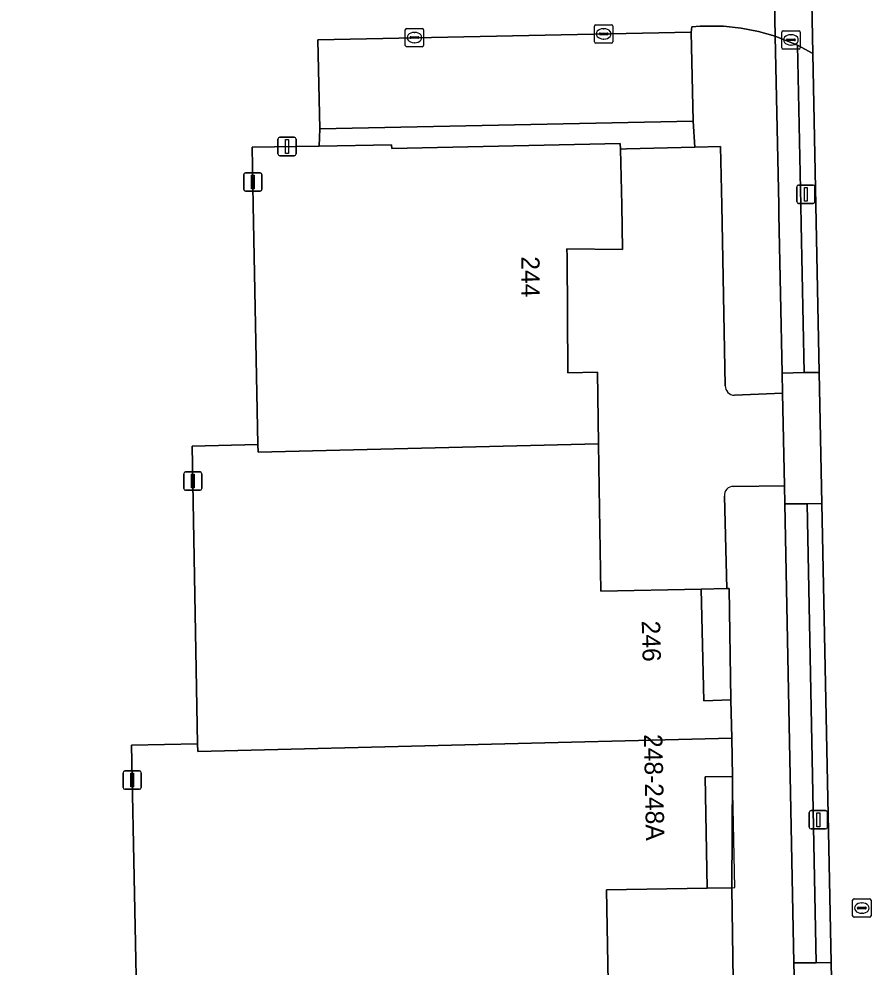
# Model space of a CAD drawing. Extents: x 161385 to 162589, y 388479 to 389756.
# Drawn here: x 162447.9 to 162494.3, y 388958.5 to 389010.1 of the extents above; entities that cross this region are included whole.
import ezdxf

# ---------------------------------------------------------------- set-up
doc = ezdxf.new("R2010")
doc.units = 0
for name, color, linetype in [('IMGEO_Berm_groen', 7, 'Continuous'), ('IMGEO_Brandkraan', 7, 'Continuous'), ('IMGEO_Erf', 7, 'Continuous'), ('IMGEO_Groenvoorziening', 7, 'Continuous'), ('IMGEO_Kolk', 7, 'Continuous'), ('IMGEO_Lichtmast', 7, 'Continuous'), ('IMGEO_Pand', 7, 'Continuous'), ('IMGEO_Pand_nummerreeks', 7, 'Continuous'), ('IMGEO_Pand_overbouw', 7, 'Continuous'), ('IMGEO_Parkeervlak_open', 7, 'Continuous'), ('IMGEO_Rijbaan_lokaal_gesloten', 7, 'Continuous'), ('IMGEO_Rijbaan_lokaal_open', 7, 'Continuous'), ('IMGEO_Rioolput', 7, 'Continuous'), ('IMGEO_Voetpad_open', 7, 'Continuous')]:
    doc.layers.add(name, color=color, linetype=linetype)

msp = doc.modelspace()

# ---------------------------------------------------------------- linework, layer by layer
at = {"layer": 'IMGEO_Berm_groen'}
for points in [[(162491.322, 389000), (162491.156, 389008.259), (162490.312, 389008.711), (162490.501, 389000), (162490.524, 388998.957), (162490.684, 388990.89), (162491.505, 388990.892)], [(162491.649, 388983.772), (162490.848, 388983.753), (162491.33, 388958.751), (162492.152, 388958.778)]]:
    msp.add_lwpolyline(points, close=True, dxfattribs=at)
at = {"layer": 'IMGEO_Brandkraan'}
for p, q in [((162489.536, 389009.503), (162490.388, 389009.503)), ((162489.461, 389008.577), (162489.461, 389009.429)), ((162489.72, 389008.997), (162489.72, 389009.009)), ((162489.763, 389009.046), (162490.161, 389009.046)), ((162489.949, 389009.283), (162489.974, 389009.283)), ((162490.204, 389009.009), (162490.204, 389008.997)), ((162490.462, 389009.429), (162490.462, 389008.577)), ((162490.388, 389008.503), (162489.536, 389008.503)), ((162490.158, 389008.96), (162489.76, 389008.96)), ((162489.972, 389008.723), (162489.947, 389008.723))]:
    msp.add_line(p, q, dxfattribs=at)
for points in [[(162489.536, 389009.503), (162490.388, 389009.503)], [(162489.461, 389008.577), (162489.461, 389009.429)], [(162490.462, 389009.429), (162490.462, 389008.577)], [(162490.388, 389008.503), (162489.536, 389008.503)]]:
    msp.add_lwpolyline(points, dxfattribs=at)
for centre, radius, start, end in [((162489.538, 389009.427), 0.0765, 91.552, 178.448), ((162489.538, 389009.427), 0.0765, 91.552, 178.448), ((162490.386, 389009.427), 0.0765, 1.552, 88.448), ((162490.386, 389009.427), 0.0765, 1.552, 88.448), ((162489.76, 389009.006), 0.0403, 85.8775, 175.7526), ((162489.757, 389008.996), 0.0366, 178.938, 274.7102), ((162490.161, 389009.003), 0.043, 264.8664, 352.4533), ((162490.165, 389009.008), 0.0386, 1.7309, 96.639), ((162489.538, 389008.579), 0.0765, 181.552, 268.448), ((162489.538, 389008.579), 0.0765, 181.552, 268.448), ((162490.386, 389008.579), 0.0765, 271.552, 358.448), ((162490.386, 389008.579), 0.0765, 271.552, 358.448)]:
    msp.add_arc(centre, radius, start, end, dxfattribs=at)
for centre, major_axis, ratio, start_param, end_param in [((162489.948, 389009.003), (-0.387, 0.002), 0.722429, 4.712389, 7.853982), ((162489.973, 389009.003), (-0.39, 0.002), 0.717154, 1.570796, 4.712389)]:
    msp.add_ellipse(centre, major_axis=major_axis, ratio=ratio, start_param=start_param, end_param=end_param, dxfattribs=at)
at = {"layer": 'IMGEO_Erf'}
for points in [[(162485.082, 388979.109), (162485.22, 388973.029), (162486.699, 388973.085), (162486.603, 388979.144), (162486.474, 388979.141)], [(162486.738, 388962.839), (162486.781, 388968.908), (162485.287, 388968.877), (162485.411, 388962.828)]]:
    msp.add_lwpolyline(points, close=True, dxfattribs=at)
at = {"layer": 'IMGEO_Groenvoorziening'}
for points in [[(162486.89, 388989.661), (162489.504, 388989.767), (162489.482, 388990.868), (162489.306, 388999.491), (162489.295, 389000), (162489.105, 389009.202), (162488.187, 389009.466), (162487.248, 389009.648), (162486.298, 389009.744), (162485.342, 389009.756), (162485.013, 389009.74), (162484.565, 389009.708), (162484.537, 389009.425), (162484.639, 389004.582), (162484.722, 389003.167), (162486.131, 389003.204), (162486.193, 389000), (162486.383, 388990.175)], [(162486.34, 388984.168), (162486.474, 388979.141), (162486.603, 388979.144), (162486.699, 388973.085), (162486.74, 388970.982), (162486.781, 388968.908), (162486.738, 388962.839), (162486.818, 388957.815), (162486.995, 388957.473), (162487.344, 388957.311), (162490.163, 388957.43), (162490.121, 388958.751), (162489.634, 388983.74), (162489.607, 388984.73), (162486.835, 388984.698)]]:
    msp.add_lwpolyline(points, dxfattribs=at)
for centre, radius, start, end in [((162486.887, 388990.165), 0.504, 178.8345, 270.3799), ((162486.83, 388984.206), 0.492, 89.458, 184.4534)]:
    msp.add_arc(centre, radius, start, end, dxfattribs=at)
at = {"layer": 'IMGEO_Kolk'}
for p, q in [((162468.969, 389008.704), (162468.969, 389009.556)), ((162469.044, 389009.63), (162469.896, 389009.63)), ((162469.97, 389009.556), (162469.97, 389008.704)), ((162479.271, 389008.903), (162479.271, 389009.755)), ((162479.346, 389009.829), (162480.198, 389009.829)), ((162479.759, 389009.609), (162479.784, 389009.609)), ((162480.272, 389009.755), (162480.272, 389008.903)), ((162469.228, 389009.124), (162469.228, 389009.136)), ((162469.666, 389009.087), (162469.268, 389009.087)), ((162469.271, 389009.173), (162469.669, 389009.173)), ((162469.457, 389009.41), (162469.482, 389009.41)), ((162469.712, 389009.136), (162469.712, 389009.124)), ((162479.53, 389009.323), (162479.53, 389009.335)), ((162479.968, 389009.286), (162479.57, 389009.286)), ((162479.573, 389009.372), (162479.971, 389009.372)), ((162479.782, 389009.049), (162479.757, 389009.049)), ((162480.014, 389009.335), (162480.014, 389009.323)), ((162469.896, 389008.63), (162469.044, 389008.63)), ((162469.48, 389008.85), (162469.455, 389008.85)), ((162480.198, 389008.829), (162479.346, 389008.829))]:
    msp.add_line(p, q, dxfattribs=at)
for points in [[(162468.969, 389008.704), (162468.969, 389009.556)], [(162469.044, 389009.63), (162469.896, 389009.63)], [(162469.97, 389009.556), (162469.97, 389008.704)], [(162479.271, 389008.903), (162479.271, 389009.755)], [(162479.346, 389009.829), (162480.198, 389009.829)], [(162480.272, 389009.755), (162480.272, 389008.903)], [(162469.896, 389008.63), (162469.044, 389008.63)], [(162480.198, 389008.829), (162479.346, 389008.829)]]:
    msp.add_lwpolyline(points, dxfattribs=at)
for centre, radius, start, end in [((162469.046, 389009.554), 0.0765, 91.552, 178.448), ((162469.046, 389009.554), 0.0765, 91.552, 178.448), ((162469.894, 389009.554), 0.0765, 1.552, 88.448), ((162469.894, 389009.554), 0.0765, 1.552, 88.448), ((162479.348, 389009.753), 0.0765, 91.552, 178.448), ((162479.348, 389009.753), 0.0765, 91.552, 178.448), ((162480.196, 389009.753), 0.0765, 1.552, 88.448), ((162480.196, 389009.753), 0.0765, 1.552, 88.448), ((162469.268, 389009.133), 0.0403, 85.8775, 175.7526), ((162469.265, 389009.123), 0.0366, 178.938, 274.7102), ((162469.669, 389009.13), 0.043, 264.8664, 352.4533), ((162469.673, 389009.135), 0.0386, 1.7309, 96.639), ((162479.57, 389009.332), 0.0403, 85.8775, 175.7526), ((162479.567, 389009.322), 0.0366, 178.938, 274.7102), ((162479.971, 389009.329), 0.043, 264.8664, 352.4533), ((162479.975, 389009.334), 0.0386, 1.7309, 96.639), ((162469.046, 389008.706), 0.0765, 181.552, 268.448), ((162469.046, 389008.706), 0.0765, 181.552, 268.448), ((162469.894, 389008.706), 0.0765, 271.552, 358.448), ((162469.894, 389008.706), 0.0765, 271.552, 358.448), ((162479.348, 389008.905), 0.0765, 181.552, 268.448), ((162479.348, 389008.905), 0.0765, 181.552, 268.448), ((162480.196, 389008.905), 0.0765, 271.552, 358.448), ((162480.196, 389008.905), 0.0765, 271.552, 358.448)]:
    msp.add_arc(centre, radius, start, end, dxfattribs=at)
for centre, major_axis, ratio, start_param, end_param in [((162479.758, 389009.329), (-0.387, 0.002), 0.722429, 4.712389, 7.853982), ((162479.783, 389009.329), (-0.39, 0.002), 0.717154, 1.570796, 4.712389), ((162469.456, 389009.13), (-0.387, 0.002), 0.722429, 4.712389, 7.853982), ((162469.481, 389009.13), (-0.39, 0.002), 0.717154, 1.570796, 4.712389)]:
    msp.add_ellipse(centre, major_axis=major_axis, ratio=ratio, start_param=start_param, end_param=end_param, dxfattribs=at)
at = {"layer": 'IMGEO_Lichtmast'}
for p, q in [((162462.037, 389002.799), (162462.037, 389003.599)), ((162462.037, 389003.599), (162462.037, 389002.799)), ((162462.137, 389003.699), (162462.927, 389003.699)), ((162462.927, 389003.699), (162462.137, 389003.699)), ((162463.027, 389003.599), (162463.027, 389002.799)), ((162463.027, 389002.799), (162463.027, 389003.599)), ((162462.927, 389002.699), (162462.137, 389002.699)), ((162462.137, 389002.699), (162462.927, 389002.699)), ((162460.275, 389001.766), (162461.065, 389001.766)), ((162461.065, 389001.766), (162460.275, 389001.766)), ((162460.175, 389000.866), (162460.175, 389001.666)), ((162460.175, 389001.666), (162460.175, 389000.866)), ((162461.165, 389001.666), (162461.165, 389000.866)), ((162461.165, 389000.866), (162461.165, 389001.666)), ((162461.065, 389000.766), (162460.275, 389000.766)), ((162460.275, 389000.766), (162461.065, 389000.766)), ((162490.276, 389000.2), (162490.276, 389001)), ((162490.276, 389001), (162490.276, 389000.2)), ((162490.376, 389001.1), (162491.166, 389001.1)), ((162491.166, 389001.1), (162490.376, 389001.1)), ((162491.266, 389001), (162491.266, 389000.2)), ((162491.266, 389000.2), (162491.266, 389001)), ((162491.166, 389000.1), (162490.376, 389000.1)), ((162490.376, 389000.1), (162491.166, 389000.1)), ((162456.908, 388984.585), (162456.908, 388985.385)), ((162456.908, 388985.385), (162456.908, 388984.585)), ((162457.008, 388985.485), (162457.798, 388985.485)), ((162457.798, 388985.485), (162457.008, 388985.485)), ((162457.898, 388985.385), (162457.898, 388984.585)), ((162457.898, 388984.585), (162457.898, 388985.385)), ((162457.798, 388984.485), (162457.008, 388984.485)), ((162457.008, 388984.485), (162457.798, 388984.485)), ((162453.609, 388968.31), (162453.609, 388969.11)), ((162453.609, 388969.11), (162453.609, 388968.31)), ((162453.709, 388969.21), (162454.499, 388969.21)), ((162454.499, 388969.21), (162453.709, 388969.21)), ((162454.599, 388969.11), (162454.599, 388968.31)), ((162454.599, 388968.31), (162454.599, 388969.11)), ((162454.499, 388968.21), (162453.709, 388968.21)), ((162453.709, 388968.21), (162454.499, 388968.21)), ((162490.958, 388966.146), (162490.958, 388966.946)), ((162490.958, 388966.946), (162490.958, 388966.146)), ((162491.058, 388967.046), (162491.848, 388967.046)), ((162491.848, 388967.046), (162491.058, 388967.046)), ((162491.948, 388966.946), (162491.948, 388966.146)), ((162491.948, 388966.146), (162491.948, 388966.946)), ((162491.848, 388966.046), (162491.058, 388966.046)), ((162491.058, 388966.046), (162491.848, 388966.046))]:
    msp.add_line(p, q, dxfattribs=at)
for points in [[(162462.457, 389003.574), (162462.607, 389003.574), (162462.607, 389002.824), (162462.457, 389002.824), (162462.457, 389003.574)], [(162460.595, 389001.641), (162460.745, 389001.641), (162460.745, 389000.891), (162460.595, 389000.891), (162460.595, 389001.641)], [(162490.696, 389000.975), (162490.846, 389000.975), (162490.846, 389000.225), (162490.696, 389000.225), (162490.696, 389000.975)], [(162457.328, 388985.36), (162457.478, 388985.36), (162457.478, 388984.61), (162457.328, 388984.61), (162457.328, 388985.36)], [(162454.029, 388969.085), (162454.179, 388969.085), (162454.179, 388968.335), (162454.029, 388968.335), (162454.029, 388969.085)], [(162491.378, 388966.921), (162491.528, 388966.921), (162491.528, 388966.171), (162491.378, 388966.171), (162491.378, 388966.921)]]:
    msp.add_lwpolyline(points, dxfattribs=at)
for centre, start, end in [((162462.137, 389003.599), 90, 180), ((162462.137, 389003.599), 90, 180), ((162462.927, 389003.599), 0, 90), ((162462.927, 389003.599), 360, 90), ((162462.137, 389002.799), 180, 270), ((162462.137, 389002.799), 180, 270), ((162462.927, 389002.799), 270, 0), ((162462.927, 389002.799), 270, 0), ((162460.275, 389001.666), 90, 180), ((162460.275, 389001.666), 90, 180), ((162461.065, 389001.666), 0, 90), ((162461.065, 389001.666), 360, 90), ((162460.275, 389000.866), 180, 270), ((162460.275, 389000.866), 180, 270), ((162461.065, 389000.866), 270, 0), ((162461.065, 389000.866), 270, 0), ((162490.376, 389001), 90, 180), ((162490.376, 389001), 90, 180), ((162491.166, 389001), 0, 90), ((162491.166, 389001), 360, 90), ((162490.376, 389000.2), 180, 270), ((162490.376, 389000.2), 180, 270), ((162491.166, 389000.2), 270, 0), ((162491.166, 389000.2), 270, 0), ((162457.008, 388985.385), 90, 180), ((162457.008, 388985.385), 90, 180), ((162457.798, 388985.385), 0, 90), ((162457.798, 388985.385), 360, 90), ((162457.008, 388984.585), 180, 270), ((162457.008, 388984.585), 180, 270), ((162457.798, 388984.585), 270, 0), ((162457.798, 388984.585), 270, 0), ((162453.709, 388969.11), 90, 180), ((162453.709, 388969.11), 90, 180), ((162454.499, 388969.11), 0, 90), ((162454.499, 388969.11), 360, 90), ((162453.709, 388968.31), 180, 270), ((162453.709, 388968.31), 180, 270), ((162454.499, 388968.31), 270, 0), ((162454.499, 388968.31), 270, 0), ((162491.058, 388966.946), 90, 180), ((162491.058, 388966.946), 90, 180), ((162491.848, 388966.946), 0, 90), ((162491.848, 388966.946), 360, 90), ((162491.058, 388966.146), 180, 270), ((162491.058, 388966.146), 180, 270), ((162491.848, 388966.146), 270, 0), ((162491.848, 388966.146), 270, 0)]:
    msp.add_arc(centre, 0.1, start, end, dxfattribs=at)
at = {"layer": 'IMGEO_Pand'}
for points in [[(162477.779, 388997.231), (162477.763, 388997.625), (162480.8, 388997.593), (162480.75, 389000), (162480.686, 389003.06), (162480.674, 389003.356), (162468.234, 389003.089), (162468.211, 389003.295), (162464.289, 389003.224), (162460.632, 389003.165), (162460.695, 389000), (162460.953, 388986.972), (162460.961, 388986.552), (162479.488, 388987.019), (162479.426, 388990.908), (162477.816, 388990.882)], [(162460.953, 388986.972), (162457.367, 388986.884), (162457.669, 388970.682), (162457.677, 388970.262), (162486.74, 388970.982), (162486.699, 388973.085), (162485.22, 388973.029), (162485.082, 388979.109), (162479.607, 388978.991), (162479.527, 388984.617), (162479.488, 388987.019), (162460.961, 388986.552)], [(162454.396, 388954.421), (162454.405, 388954.001), (162480.076, 388954.684), (162479.919, 388962.732), (162485.411, 388962.828), (162485.287, 388968.877), (162486.781, 388968.908), (162486.74, 388970.982), (162457.677, 388970.262), (162457.669, 388970.682), (162454.065, 388970.609)]]:
    msp.add_lwpolyline(points, close=True, dxfattribs=at)
at = {"layer": 'IMGEO_Pand_overbouw'}
for points in [[(162486.603, 388979.144), (162486.474, 388979.141), (162485.082, 388979.109), (162485.22, 388973.018), (162486.699, 388973.085)], [(162486.781, 388968.908), (162485.287, 388968.877), (162485.411, 388962.828), (162486.901, 388962.854)]]:
    msp.add_lwpolyline(points, close=True, dxfattribs=at)
at = {"layer": 'IMGEO_Parkeervlak_open'}
msp.add_lwpolyline([(162464.21, 389009.005), (162464.312, 389004.165), (162484.639, 389004.582), (162484.537, 389009.425)], close=True, dxfattribs=at)
for points in [[(162486.383, 388990.175), (162486.193, 389000), (162486.131, 389003.204), (162484.722, 389003.167), (162481.01, 389003.069), (162480.686, 389003.06), (162480.75, 389000), (162480.8, 388997.593), (162477.763, 388997.625), (162477.779, 388997.231), (162477.816, 388990.882), (162479.426, 388990.908), (162479.488, 388987.019), (162479.527, 388984.617), (162479.607, 388978.991), (162485.082, 388979.109), (162486.474, 388979.141), (162486.34, 388984.168)], [(162486.835, 388984.698), (162489.607, 388984.73), (162489.504, 388989.767), (162486.89, 388989.661)], [(162485.411, 388962.828), (162479.919, 388962.732), (162480.076, 388954.684)], [(162486.738, 388962.839), (162485.411, 388962.828)], [(162490.163, 388957.43), (162487.344, 388957.311), (162486.995, 388957.473), (162486.818, 388957.815), (162486.738, 388962.839)]]:
    msp.add_lwpolyline(points, dxfattribs=at)
for centre, radius, start, end in [((162486.887, 388990.165), 0.504, 178.8345, 270.3799), ((162486.83, 388984.206), 0.492, 89.458, 184.4534)]:
    msp.add_arc(centre, radius, start, end, dxfattribs=at)
at = {"layer": 'IMGEO_Rijbaan_lokaal_gesloten'}
msp.add_lwpolyline([(162490.951, 389018.401), (162491.156, 389008.259), (162491.322, 389000), (162491.505, 388990.892), (162491.649, 388983.772), (162492.152, 388958.778), (162492.294, 388951.732), (162492.794, 388926.923), (162492.96, 388918.653), (162493.222, 388905.666), (162493.34, 388899.826), (162493.479, 388892.905), (162493.608, 388886.494)], dxfattribs=at)
at = {"layer": 'IMGEO_Rijbaan_lokaal_open'}
msp.add_lwpolyline([(162447.511, 388938.068), (162451.11, 388938.136), (162450.794, 388954.344), (162454.396, 388954.421), (162454.065, 388970.609), (162457.669, 388970.682), (162457.367, 388986.884), (162460.953, 388986.972), (162460.695, 389000), (162460.632, 389003.165), (162464.289, 389003.224), (162464.312, 389004.165), (162464.21, 389009.005), (162484.537, 389009.425), (162484.565, 389009.708), (162485.013, 389009.74), (162485.342, 389009.756), (162486.298, 389009.744), (162487.248, 389009.648), (162488.187, 389009.466), (162489.105, 389009.202), (162488.94, 389017.541)], dxfattribs=at)
at = {"layer": 'IMGEO_Rioolput'}
for p, q in [((162493.32, 388961.314), (162493.32, 388962.166)), ((162493.395, 388962.24), (162494.247, 388962.24)), ((162493.808, 388962.02), (162493.833, 388962.02)), ((162494.321, 388962.166), (162494.321, 388961.314)), ((162493.579, 388961.734), (162493.579, 388961.746)), ((162494.017, 388961.697), (162493.619, 388961.697)), ((162493.622, 388961.783), (162494.02, 388961.783)), ((162494.063, 388961.746), (162494.063, 388961.734)), ((162494.247, 388961.24), (162493.395, 388961.24)), ((162493.831, 388961.46), (162493.806, 388961.46))]:
    msp.add_line(p, q, dxfattribs=at)
for points in [[(162493.32, 388961.314), (162493.32, 388962.166)], [(162493.395, 388962.24), (162494.247, 388962.24)], [(162494.321, 388962.166), (162494.321, 388961.314)], [(162494.247, 388961.24), (162493.395, 388961.24)]]:
    msp.add_lwpolyline(points, dxfattribs=at)
for centre, radius, start, end in [((162493.397, 388962.164), 0.0765, 91.552, 178.448), ((162493.397, 388962.164), 0.0765, 91.552, 178.448), ((162494.245, 388962.164), 0.0765, 1.552, 88.448), ((162494.245, 388962.164), 0.0765, 1.552, 88.448), ((162493.619, 388961.743), 0.0403, 85.8775, 175.7526), ((162493.616, 388961.733), 0.0366, 178.938, 274.7102), ((162494.02, 388961.74), 0.043, 264.8664, 352.4533), ((162494.024, 388961.745), 0.0386, 1.7309, 96.639), ((162493.397, 388961.316), 0.0765, 181.552, 268.448), ((162493.397, 388961.316), 0.0765, 181.552, 268.448), ((162494.245, 388961.316), 0.0765, 271.552, 358.448), ((162494.245, 388961.316), 0.0765, 271.552, 358.448)]:
    msp.add_arc(centre, radius, start, end, dxfattribs=at)
for centre, major_axis, ratio, start_param, end_param in [((162493.807, 388961.74), (-0.387, 0.002), 0.722429, 4.712389, 7.853982), ((162493.832, 388961.74), (-0.39, 0.002), 0.717154, 1.570796, 4.712389)]:
    msp.add_ellipse(centre, major_axis=major_axis, ratio=ratio, start_param=start_param, end_param=end_param, dxfattribs=at)
at = {"layer": 'IMGEO_Voetpad_open'}
for points in [[(162489.105, 389009.202), (162490.312, 389008.711), (162491.156, 389008.259), (162490.951, 389018.401), (162490.144, 389018.011), (162488.94, 389017.541)], [(162490.684, 388990.89), (162490.524, 388998.957), (162490.501, 389000), (162490.312, 389008.711), (162489.105, 389009.202), (162489.295, 389000), (162489.306, 388999.491), (162489.482, 388990.868)], [(162464.289, 389003.224), (162468.211, 389003.295), (162468.234, 389003.089), (162480.674, 389003.356), (162480.686, 389003.06), (162481.01, 389003.069), (162484.722, 389003.167), (162484.639, 389004.582), (162464.312, 389004.165)], [(162490.848, 388983.753), (162491.649, 388983.772), (162491.505, 388990.892), (162490.684, 388990.89), (162489.482, 388990.868), (162489.504, 388989.767), (162489.607, 388984.73), (162489.634, 388983.74)], [(162491.33, 388958.751), (162490.848, 388983.753), (162489.634, 388983.74), (162490.121, 388958.751)], [(162491.451, 388951.716), (162492.294, 388951.732), (162492.152, 388958.778), (162491.33, 388958.751), (162490.121, 388958.751), (162490.163, 388957.43), (162490.236, 388952.36), (162490.263, 388951.7)]]:
    msp.add_lwpolyline(points, close=True, dxfattribs=at)

# ---------------------------------------------------------------- texts
at = {"layer": 'IMGEO_Pand_nummerreeks'}
for s, rotation, p in [('244', 270.3321, (162475.279, 388997.219)), ('246', 271.3002, (162481.84, 388977.373)), ('248-248A', 271.1744, (162481.959, 388971.201))]:
    msp.add_text(s, height=1, rotation=rotation, dxfattribs=at).set_placement(p)

doc.saveas('drawing.dxf')
